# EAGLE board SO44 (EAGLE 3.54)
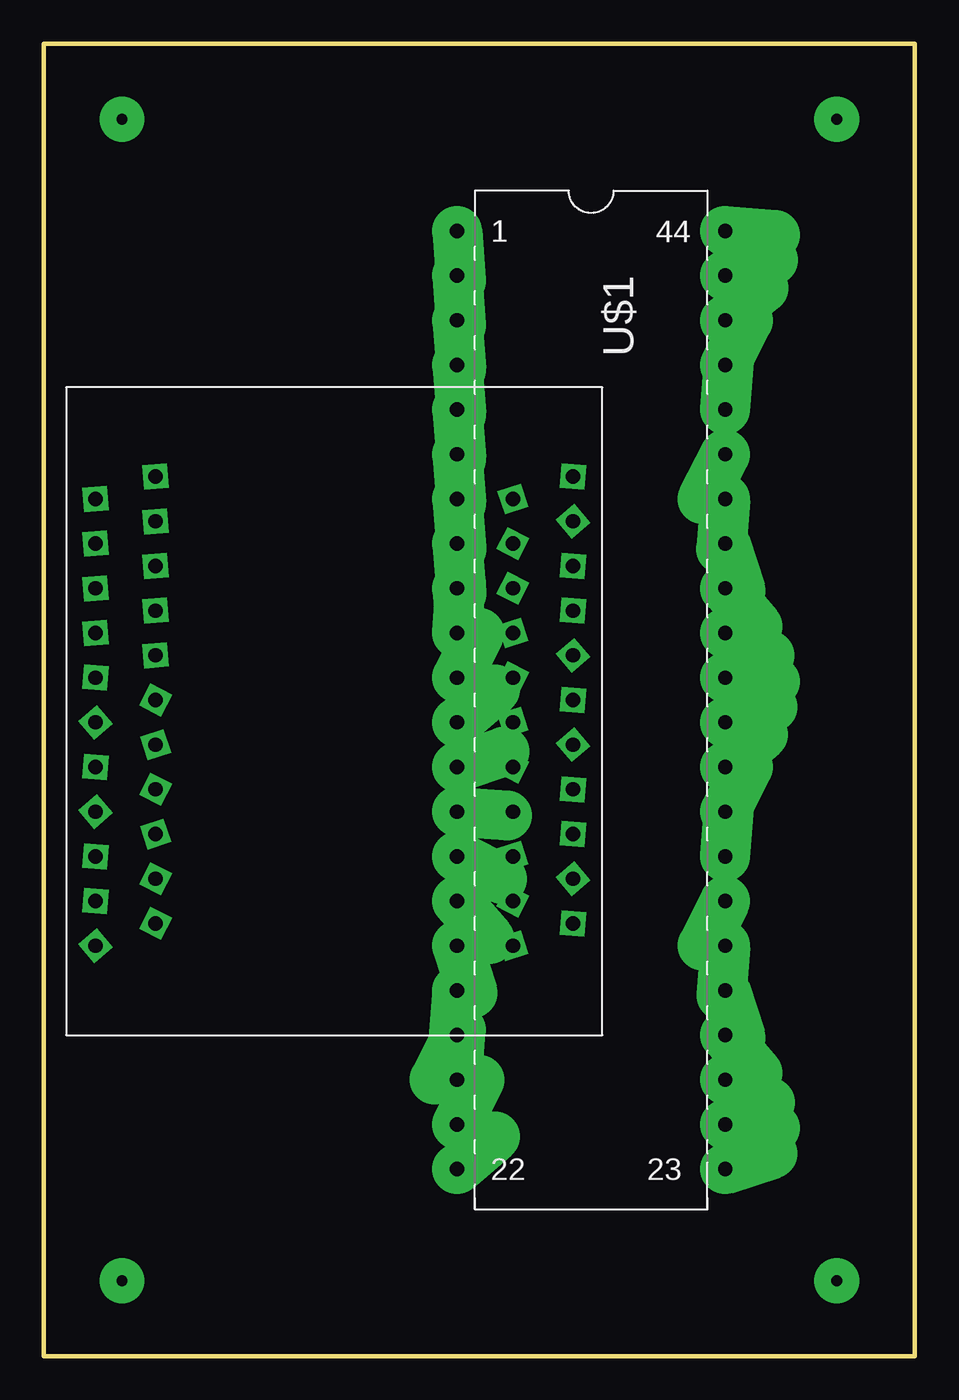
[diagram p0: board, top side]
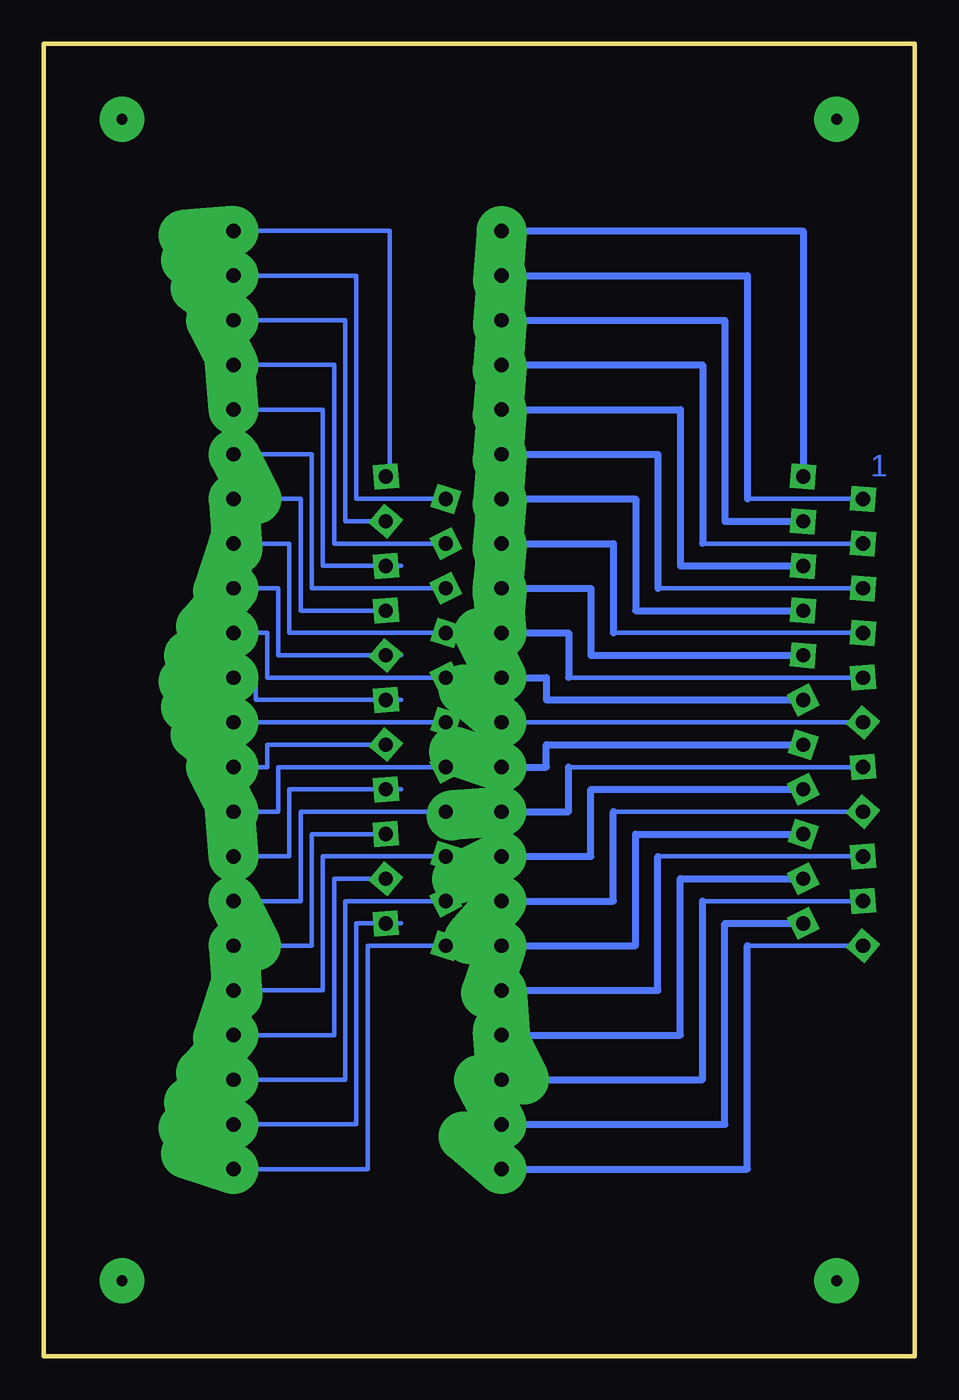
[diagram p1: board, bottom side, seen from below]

Size 49.51 x 74.6 mm. Coordinates in mm from the lower left corner, seen from the top.
Outline: 0,0 49.51,0 49.51,74.6 0,74.6 0,0
Copper layers used: Bottom

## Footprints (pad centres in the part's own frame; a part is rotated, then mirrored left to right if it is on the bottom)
L44 = drill 0.813 pad 2.845 offset:  -29.21,-7.62;  -26.67,-7.62;  -24.13,-7.62;  -21.59,-7.62;  -19.05,-7.62;  -16.51,-7.62;  -13.97,-7.62;  -11.43,-7.62;  -8.89,-7.62;  -6.35,-7.62;  -3.81,-7.62;  -1.27,-7.62;  1.27,-7.62;  3.81,-7.62;  6.35,-7.62;  8.89,-7.62;  11.43,-7.62;  13.97,-7.62;  16.51,-7.62;  19.05,-7.62;  21.59,-7.62;  24.13,-7.62;  24.13,7.62;  21.59,7.62;  19.05,7.62;  16.51,7.62;  13.97,7.62;  11.43,7.62;  8.89,7.62;  6.35,7.62;  3.81,7.62;  1.27,7.62;  -1.27,7.62;  -3.81,7.62;  -6.35,7.62;  -8.89,7.62;  -11.43,7.62;  -13.97,7.62;  -16.51,7.62;  -19.05,7.62;  -21.59,7.62;  -24.13,7.62;  -26.67,7.62;  -29.21,7.62
44SOCK = drill 0.813 pad 1.397 square:  -13.57,3.81;  -13.57,1.27;  -13.57,-1.27;  -13.57,-3.81;  -13.57,-6.35;  -13.57,-8.89;  -13.57,-11.43;  -13.57,6.35;  -13.57,8.89;  -13.57,11.43;  -13.57,13.97;  -10.16,15.24;  -10.16,12.7;  -10.16,10.16;  -10.16,7.62;  -10.16,5.08;  -10.16,2.54;  -10.16,0;  -10.16,-2.54;  -10.16,-5.08;  -10.16,-7.62;  -10.16,-10.16;  10.16,13.97;  13.57,15.24;  13.57,12.7;  13.57,10.16;  13.57,7.62;  13.57,5.08;  13.57,2.54;  13.57,0;  13.57,-2.54;  13.57,-5.08;  13.57,-7.62;  13.57,-10.16;  10.16,11.43;  10.16,8.89;  10.16,6.35;  10.16,3.81;  10.16,1.27;  10.16,-1.27;  10.16,-3.81;  10.16,-6.35;  10.16,-8.89;  10.16,-11.43

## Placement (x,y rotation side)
U$1  DIL44SOKEL  [L44]  31.11,34.76 270 top
U$2  SO44SOKEL  [44SOCK]  16.5,34.76 0 top

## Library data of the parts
U$1 U$2 = DIL-E

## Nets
N$1: U$1. U$2.
N$2: U$1. U$2.
N$3: U$1. U$2.
N$4: U$1. U$2.
N$5: U$1. U$2.
N$6: U$1. U$2.
N$7: U$1. U$2.
N$8: U$1. U$2.
N$9: U$1. U$2.
N$10: U$1. U$2.
N$11: U$1. U$2.
N$12: U$1. U$2.
N$13: U$1. U$2.
N$14: U$1. U$2.
N$15: U$1. U$2.
N$16: U$1. U$2.
N$17: U$1. U$2.
N$18: U$1. U$2.
N$19: U$1. U$2.
N$20: U$1. U$2.
N$21: U$1. U$2.
N$22: U$1. U$2.
N$23: U$1. U$2.
N$24: U$1. U$2.
N$25: U$1. U$2.
N$26: U$1. U$2.
N$27: U$1. U$2.
N$28: U$1. U$2.
N$29: U$1. U$2.
N$30: U$1. U$2.
N$31: U$1. U$2.
N$32: U$1. U$2.
N$33: U$1. U$2.
N$34: U$1. U$2.
N$35: U$1. U$2.
N$36: U$1. U$2.
N$37: U$1. U$2.
N$38: U$1. U$2.
N$39: U$1. U$2.
N$40: U$1. U$2.
N$41: U$1. U$2.
N$42: U$1. U$2.
N$43: U$1. U$2.
N$44: U$1. U$2.

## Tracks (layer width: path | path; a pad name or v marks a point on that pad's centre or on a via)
N$1
  Bottom 0.406: 23.49,63.97 6.34,63.97 6.34,50
N$2
  Bottom 0.254: 9.52,48.73 2.93,48.73
  Bottom 0.406: 23.49,61.43 9.52,61.43 9.52,48.73 | 3.17,48.73 2.93,48.73
N$3
  Bottom 0.406: 23.49,58.89 10.79,58.89 10.79,47.46 6.34,47.46
N$4
  Bottom 0.254: 12.06,46.19 2.93,46.19
  Bottom 0.406: 23.49,56.35 12.06,56.35 12.06,46.19 | 3.17,46.19 2.93,46.19
N$5
  Bottom 0.406: 23.49,53.81 13.33,53.81 13.33,44.92 6.34,44.92
N$6
  Bottom 0.254: 14.6,43.65 2.93,43.65
  Bottom 0.406: 23.49,51.27 14.6,51.27 14.6,43.65 | 3.17,43.65 2.93,43.65
N$7
  Bottom 0.406: 23.49,48.73 15.87,48.73 15.87,42.38 6.34,42.38
N$8
  Bottom 0.254: 17.14,41.11 2.93,41.11
  Bottom 0.406: 23.49,46.19 17.14,46.19 17.14,41.11 | 3.17,41.11 2.93,41.11
N$9
  Bottom 0.406: 23.49,43.65 18.41,43.65 18.41,39.84 6.34,39.84
N$10
  Bottom 0.254: 19.68,38.57 2.93,38.57
  Bottom 0.406: 23.49,41.11 19.68,41.11 19.68,38.57 | 3.17,38.57 2.93,38.57
N$11
  Bottom 0.406: 23.49,38.57 20.95,38.57 20.95,37.3 6.34,37.3
N$12
  Bottom 0.254: 23.49,36.03 2.93,36.03
  Bottom 0.406: 3.17,36.03 2.93,36.03
N$13
  Bottom 0.406: 23.49,33.49 20.95,33.49 20.95,34.76 6.34,34.76
N$14
  Bottom 0.254: 19.68,33.49 2.93,33.49
  Bottom 0.406: 23.49,30.95 19.68,30.95 19.68,33.49 | 3.17,33.49 2.93,33.49
N$15
  Bottom 0.406: 23.49,28.41 18.41,28.41 18.41,32.22 6.34,32.22
N$16
  Bottom 0.254: 17.14,30.95 2.93,30.95
  Bottom 0.406: 23.49,25.87 17.14,25.87 17.14,30.95 | 3.17,30.95 2.93,30.95
N$17
  Bottom 0.406: 23.49,23.33 15.87,23.33 15.87,29.68 6.34,29.68
N$18
  Bottom 0.254: 14.6,28.41 2.93,28.41
  Bottom 0.406: 23.49,20.79 14.6,20.79 14.6,28.41 | 3.17,28.41 2.93,28.41
N$19
  Bottom 0.406: 23.49,18.25 13.33,18.25 13.33,27.14 6.34,27.14
N$20
  Bottom 0.254: 12.06,25.87 2.93,25.87
  Bottom 0.406: 23.49,15.71 12.06,15.71 12.06,25.87 | 3.17,25.87 2.93,25.87
N$21
  Bottom 0.406: 23.49,13.17 10.79,13.17 10.79,24.6 6.34,24.6
N$22
  Bottom 0.254: 9.52,23.33 2.93,23.33
  Bottom 0.406: 23.49,10.63 9.52,10.63 9.52,23.33 | 3.17,23.33 2.93,23.33
N$23
  Bottom 0.254: 30.07,50 29.84,50 29.84,63.97 U$1.
N$24
  Bottom 0.254: 38.73,61.43 31.75,61.43 31.75,48.73 26.67,48.73
N$25
  Bottom 0.254: 38.73,58.89 32.38,58.89 32.38,47.46 30.07,47.46
N$26
  Bottom 0.254: 38.73,56.35 33.02,56.35 33.02,46.19 26.67,46.19
N$27
  Bottom 0.254: 38.73,53.81 33.65,53.81 33.65,44.92 30.07,44.92 29.21,44.92
N$28
  Bottom 0.254: 38.73,51.27 34.28,51.27 34.28,43.65 26.67,43.65
N$29
  Bottom 0.254: 38.73,48.73 34.92,48.73 34.92,42.38 30.07,42.38
N$30
  Bottom 0.254: 38.73,46.19 35.56,46.19 35.56,41.11 26.67,41.11
N$31
  Bottom 0.254: 38.73,43.65 36.19,43.65 36.19,39.84 30.07,39.84 29.21,39.84
N$32
  Bottom 0.254: 38.73,41.11 36.83,41.11 36.83,38.57 26.67,38.57
N$33
  Bottom 0.254: 38.73,38.57 37.46,38.57 37.46,37.3 30.07,37.3 29.21,37.3
N$34
  Bottom 0.254: 38.73,36.03 26.67,36.03
N$35
  Bottom 0.254: 38.73,33.49 36.83,33.49 36.83,34.76 30.07,34.76
N$36
  Bottom 0.254: 38.73,30.95 36.19,30.95 36.19,33.49 26.67,33.49
N$37
  Bottom 0.254: 38.73,28.41 35.56,28.41 35.56,32.22 30.07,32.22 29.21,32.22
N$38
  Bottom 0.254: 38.73,25.87 34.92,25.87 34.92,30.95 26.67,30.95
N$39
  Bottom 0.254: 38.73,23.33 34.28,23.33 34.28,29.68 30.07,29.68
N$40
  Bottom 0.254: 38.73,20.79 33.65,20.79 33.65,28.41 26.67,28.41
N$41
  Bottom 0.254: 38.73,18.25 33.02,18.25 33.02,27.14 30.07,27.14
N$42
  Bottom 0.254: 38.73,15.71 32.38,15.71 32.38,25.87 26.67,25.87
N$43
  Bottom 0.254: 38.73,13.17 31.75,13.17 31.75,24.6 30.07,24.6 29.21,24.6
N$44
  Bottom 0.254: 38.73,10.63 31.11,10.63 31.11,23.33 U$2.
N$45  (via drill 0.61 pad 2.54)
  other vias: 45.08,70.32
N$46  (via drill 0.61 pad 2.54)
  other vias: 4.44,70.32
N$47  (via drill 0.61 pad 2.54)
  other vias: 45.08,4.28
N$48  (via drill 0.61 pad 2.54)
  other vias: 4.44,4.28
